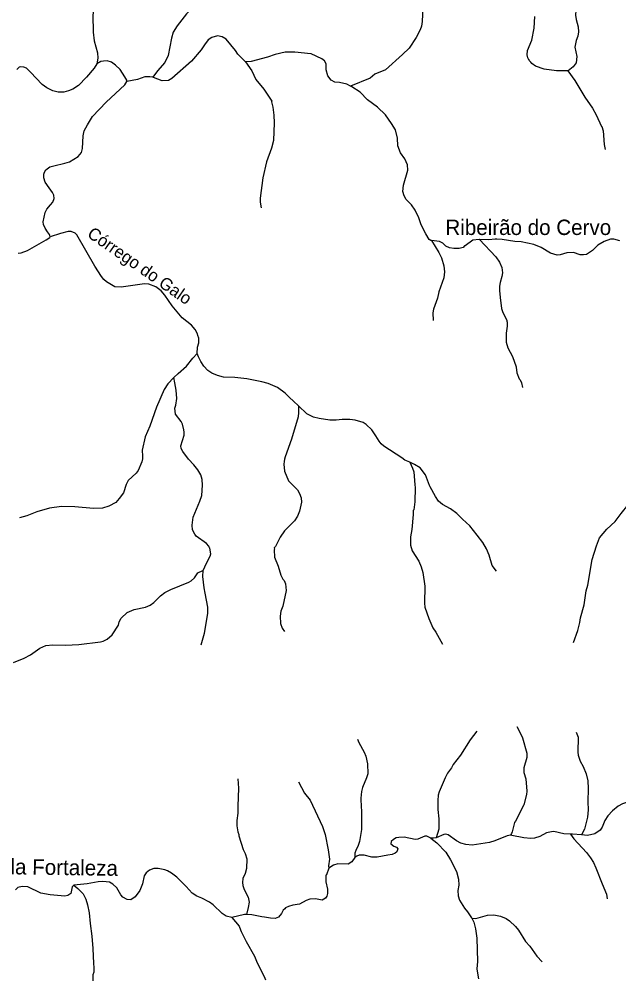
# Model space of a CAD drawing. Extents: x 396 to 422.2, y 7649.8 to 7677.6.
# Drawn here: x 409.11 to 413.01, y 7649.9 to 7656.16 of the extents above; entities that cross this region are included whole.
import ezdxf
from ezdxf.enums import TextEntityAlignment as Align

# ---------------------------------------------------------------- set-up
doc = ezdxf.new("R2010")
doc.units = 0
doc.header["$LTSCALE"] = 0.032
doc.layers.add('2', color=7, linetype='Continuous', lineweight=25)
doc.layers.add('7', color=7, linetype='Continuous', lineweight=25)
doc.layers.add('61', color=7, linetype='Continuous')

msp = doc.modelspace()

# ---------------------------------------------------------------- linework, layer by layer
at = {"layer": '2'}
for points in [[(409.6179, 7655.872), (409.5999, 7655.8432), (409.5497, 7655.7852), (409.4976, 7655.7301), (409.4602, 7655.7065), (409.4327, 7655.6957), (409.4032, 7655.6878), (409.3668, 7655.6878), (409.3314, 7655.6967), (409.2931, 7655.7164), (409.2626, 7655.737), (409.1869, 7655.8176), (409.1594, 7655.8432), (409.1417, 7655.8511), (409.123, 7655.853), (409.1131, 7655.8511), (409.0962, 7655.8359)], [(409.8123, 7655.7577), (409.8123, 7655.7665), (409.7995, 7655.7881), (409.768, 7655.8344), (409.7395, 7655.8639), (409.712, 7655.8835), (409.6844, 7655.8904), (409.6608, 7655.8894), (409.6431, 7655.8865), (409.6179, 7655.872)], [(409.1053, 7654.6387), (409.1259, 7654.6426), (409.1662, 7654.6564), (409.2882, 7654.7262), (409.3108, 7654.7409), (409.3137, 7654.7468), (409.3088, 7654.7616), (409.297, 7654.7793), (409.2813, 7654.8019), (409.2705, 7654.8255), (409.2675, 7654.8442), (409.2813, 7654.9051), (409.2921, 7654.9258), (409.3167, 7654.9533), (409.3314, 7654.971), (409.3393, 7654.9956), (409.3383, 7655.0162), (409.3295, 7655.0349), (409.3068, 7655.0644), (409.2823, 7655.1018), (409.2734, 7655.1303), (409.2724, 7655.1529), (409.2764, 7655.1667), (409.2852, 7655.1824), (409.3127, 7655.2011), (409.3383, 7655.209), (409.4101, 7655.2247), (409.4386, 7655.2336), (409.4956, 7655.269), (409.5183, 7655.2945), (409.5251, 7655.3201), (409.5291, 7655.4037), (409.535, 7655.4351), (409.5556, 7655.4754), (409.59, 7655.5295), (409.6775, 7655.6229), (409.7995, 7655.736), (409.8123, 7655.7577)]]:
    msp.add_lwpolyline(points, dxfattribs=at)
at = {"layer": '7'}
for points in [[(409.8043, 7656.6946), (409.791, 7656.6689), (409.7845, 7656.6465), (409.7771, 7656.5897), (409.7704, 7656.5671), (409.7494, 7656.5321), (409.6976, 7656.4627), (409.6654, 7656.4129), (409.6394, 7656.3547), (409.6319, 7656.3281), (409.6035, 7656.2649), (409.5969, 7656.2391), (409.5906, 7656.1891), (409.5938, 7656.0784), (409.6002, 7656.0219), (409.6225, 7655.9433), (409.624, 7655.9098), (409.6179, 7655.872)], [(410.6349, 7656.6002), (410.6027, 7656.5501), (410.6, 7656.5506), (410.5967, 7656.5421), (410.5554, 7656.4912), (410.5149, 7656.4492), (410.4637, 7656.3779), (410.4272, 7656.3448), (410.2668, 7656.2547), (410.2375, 7656.2342), (410.2, 7656.1964), (410.1399, 7656.12), (410.1127, 7656.0776), (410.1022, 7656.0384), (410.0814, 7655.9254), (410.0586, 7655.8798), (410.0128, 7655.8262), (409.9816, 7655.7845)], [(412.7824, 7656.4039), (412.7752, 7656.3967), (412.7632, 7656.3764), (412.7407, 7656.2937), (412.7406, 7656.2491), (412.7311, 7656.2184), (412.7302, 7656.1897), (412.7342, 7656.1594), (412.7469, 7656.1123), (412.7494, 7656.0809), (412.7438, 7656.0525), (412.7342, 7656.0238), (412.7264, 7655.9814), (412.7374, 7655.9201), (412.7341, 7655.8787), (412.7151, 7655.8515), (412.6816, 7655.8271), (412.6802, 7655.8271)], [(411.7396, 7656.2876), (411.7323, 7656.148), (411.7283, 7656.1172), (411.7206, 7656.0939), (411.6937, 7656.0436), (411.6475, 7655.9749), (411.6041, 7655.9316), (411.4941, 7655.8334), (411.4248, 7655.8048), (411.3936, 7655.7778), (411.2674, 7655.7264)], [(412.6802, 7655.8271), (412.6055, 7655.8268), (412.5261, 7655.8371), (412.4687, 7655.8576), (412.4456, 7655.8731), (412.4391, 7655.8834), (412.4299, 7655.8913), (412.4294, 7655.8969), (412.4263, 7655.8982), (412.4198, 7655.9113), (412.4153, 7655.9297), (412.4167, 7655.9581), (412.4465, 7656.0262), (412.4611, 7656.1045), (412.4663, 7656.18)], [(410.585, 7655.8843), (410.5844, 7655.8843), (410.5332, 7655.934), (410.5186, 7655.958), (410.4587, 7656.0328), (410.4319, 7656.0479), (410.4024, 7656.0543), (410.3643, 7656.0441), (410.3419, 7656.0291), (410.3168, 7655.9966), (410.2968, 7655.9625), (410.2323, 7655.8889), (410.106, 7655.7769), (410.084, 7655.7643)], [(411.2674, 7655.7264), (411.2424, 7655.7396), (411.1956, 7655.7499), (411.1644, 7655.7517), (411.1413, 7655.7649), (411.1183, 7655.7929), (411.1078, 7655.8321), (411.1087, 7655.8709), (411.0987, 7655.892), (411.0795, 7655.9048), (411.0108, 7655.9372), (411.0098, 7655.9377), (410.9037, 7655.9481), (410.8426, 7655.9472), (410.7777, 7655.9324), (410.7264, 7655.9151), (410.6208, 7655.8863), (410.585, 7655.8843)], [(410.585, 7655.8843), (410.6242, 7655.8273), (410.652, 7655.7702), (410.7027, 7655.7072), (410.7546, 7655.6299), (410.7534, 7655.6244), (410.7627, 7655.5907), (410.7692, 7655.5389), (410.7708, 7655.4876), (410.7652, 7655.3727), (410.7534, 7655.3227), (410.7214, 7655.2331), (410.6975, 7655.131), (410.6792, 7654.9969), (410.6802, 7654.9711), (410.6864, 7654.9353)], [(412.6802, 7655.8271), (412.7258, 7655.7629), (412.7908, 7655.6553), (412.8413, 7655.5833), (412.8644, 7655.5402), (412.8987, 7655.4649), (412.9017, 7655.4635), (412.9098, 7655.4354), (412.9169, 7655.3479), (412.9233, 7655.3149)], [(409.9816, 7655.7845), (409.961, 7655.788), (409.9302, 7655.788), (409.8812, 7655.7696), (409.8123, 7655.7577)], [(410.084, 7655.7643), (410.042, 7655.7612), (409.9866, 7655.7836), (409.9816, 7655.7845)], [(411.7934, 7654.7225), (411.7901, 7654.7229), (411.7789, 7654.729), (411.7564, 7654.7658), (411.727, 7654.8247), (411.7118, 7654.8691), (411.6878, 7654.9196), (411.6629, 7654.9546), (411.6288, 7654.9887), (411.6149, 7655.0127), (411.608, 7655.0413), (411.6121, 7655.0825), (411.6396, 7655.1803), (411.637, 7655.2149), (411.619, 7655.2547), (411.591, 7655.2926), (411.5737, 7655.3375), (411.572, 7655.3874), (411.5586, 7655.4428), (411.5341, 7655.4847), (411.4935, 7655.5398), (411.4413, 7655.5893), (411.3779, 7655.6384), (411.3292, 7655.6867), (411.2757, 7655.722), (411.2674, 7655.7264)], [(410.2706, 7653.986), (410.2715, 7654.0278), (410.2795, 7654.0572), (410.2795, 7654.0859), (410.2745, 7654.1042), (410.2718, 7654.1139), (410.2572, 7654.1421), (410.2328, 7654.171), (410.1731, 7654.2196), (410.1065, 7654.298), (410.0596, 7654.3668), (410.0359, 7654.3941), (410.0004, 7654.4216), (409.9558, 7654.4376), (409.9283, 7654.4399), (409.7762, 7654.4178), (409.7339, 7654.421), (409.6807, 7654.453), (409.6621, 7654.4689), (409.6474, 7654.4869), (409.604, 7654.5551), (409.4876, 7654.759), (409.4757, 7654.7693), (409.4514, 7654.7797), (409.4305, 7654.7799), (409.3813, 7654.7684), (409.3137, 7654.7468)], [(412.1051, 7654.7287), (412.1034, 7654.7288), (412.0627, 7654.7253), (412.0133, 7654.6879), (412.0075, 7654.6869), (411.9998, 7654.6774), (411.9731, 7654.6712), (411.9393, 7654.6698), (411.9104, 7654.6735), (411.8858, 7654.6857), (411.8681, 7654.7039), (411.8453, 7654.7165), (411.7934, 7654.7225)], [(411.7934, 7654.7225), (411.8417, 7654.6438), (411.8588, 7654.6098), (411.8736, 7654.5582), (411.8786, 7654.5182), (411.8734, 7654.4786), (411.841, 7654.389), (411.8315, 7654.3459), (411.8069, 7654.2748), (411.8028, 7654.2517), (411.8045, 7654.2016)], [(413.0181, 7654.7191), (412.9783, 7654.7302), (412.9575, 7654.7302), (412.9161, 7654.7159), (412.8744, 7654.6909), (412.8406, 7654.6564), (412.8012, 7654.6306), (412.7814, 7654.6282), (412.7602, 7654.6297), (412.7167, 7654.644), (412.6736, 7654.6409), (412.6303, 7654.6281), (412.6098, 7654.6267), (412.5681, 7654.6403), (412.5066, 7654.677), (412.4596, 7654.6952), (412.377, 7654.7135), (412.3359, 7654.7159), (412.253, 7654.7286), (412.218, 7654.731), (412.2074, 7654.7299), (412.1652, 7654.7255), (412.1051, 7654.7287)], [(412.1051, 7654.7287), (412.2121, 7654.6168), (412.2358, 7654.5819), (412.2497, 7654.5473), (412.2541, 7654.5126), (412.2516, 7654.4875), (412.239, 7654.4492), (412.2351, 7654.426), (412.2352, 7654.3975), (412.2408, 7654.3511), (412.2495, 7654.2797), (412.2557, 7654.2594), (412.2828, 7654.202), (412.2829, 7654.1946), (412.286, 7654.1924), (412.2862, 7654.1642), (412.2798, 7654.1196), (412.2799, 7654.0597), (412.2895, 7654.0243), (412.3202, 7653.9681), (412.3435, 7653.8993), (412.3436, 7653.8986), (412.3484, 7653.8619), (412.3629, 7653.821), (412.3707, 7653.8145), (412.3784, 7653.7959), (412.385, 7653.7662)], [(410.1183, 7653.8308), (410.1463, 7653.8568), (410.2012, 7653.9038), (410.242, 7653.9575), (410.2706, 7653.986)], [(410.9288, 7653.6457), (410.8961, 7653.6768), (410.8696, 7653.701), (410.8421, 7653.7284), (410.7931, 7653.7653), (410.7317, 7653.7914), (410.6892, 7653.8032), (410.5935, 7653.8212), (410.5148, 7653.8315), (410.4403, 7653.8331), (410.4022, 7653.8426), (410.3661, 7653.8587), (410.3398, 7653.8771), (410.3136, 7653.9043), (410.2927, 7653.9353), (410.2774, 7653.9655), (410.2706, 7653.986)], [(410.1183, 7653.8308), (410.0799, 7653.7891), (410.0551, 7653.7517), (410.0062, 7653.6381), (409.9628, 7653.5146), (409.931, 7653.4444), (409.9112, 7653.3574), (409.9115, 7653.355), (409.9151, 7653.3207), (409.9143, 7653.3012), (409.9094, 7653.2817), (409.8863, 7653.2261), (409.8733, 7653.2075), (409.8219, 7653.1608), (409.8077, 7653.1344), (409.7899, 7653.0811), (409.7622, 7653.0422), (409.7404, 7653.0173), (409.6956, 7652.9931), (409.6534, 7652.9811), (409.5961, 7652.9791), (409.4749, 7652.9885), (409.3885, 7652.9902), (409.3098, 7652.9797), (409.2279, 7652.9571), (409.1612, 7652.931), (409.1137, 7652.9176)], [(410.306, 7652.5744), (410.3086, 7652.5756), (410.3294, 7652.6231), (410.3552, 7652.6669), (410.3593, 7652.6821), (410.3531, 7652.7195), (410.3493, 7652.7215), (410.3448, 7652.734), (410.3308, 7652.7498), (410.2642, 7652.7987), (410.2539, 7652.8103), (410.2398, 7652.839), (410.2374, 7652.8686), (410.2431, 7652.9223), (410.2874, 7653.0265), (410.3003, 7653.0632), (410.3043, 7653.1307), (410.3018, 7653.1664), (410.2925, 7653.1972), (410.2737, 7653.2297), (410.2482, 7653.2616), (410.2131, 7653.2982), (410.176, 7653.3493), (410.1658, 7653.3678), (410.1633, 7653.3861), (410.1854, 7653.4559), (410.1845, 7653.4752), (410.1838, 7653.4909), (410.1743, 7653.526), (410.1657, 7653.5433), (410.1281, 7653.5915), (410.1249, 7653.6302), (410.1319, 7653.6513), (410.1377, 7653.6929), (410.1329, 7653.7474), (410.1248, 7653.7957), (410.1183, 7653.8308)], [(410.9288, 7653.6457), (410.9287, 7653.6019), (410.9255, 7653.5739), (410.8822, 7653.4296), (410.8417, 7653.3136), (410.8382, 7653.2988), (410.8347, 7653.2839), (410.8338, 7653.2676), (410.8383, 7653.2212), (410.8645, 7653.1574), (410.9222, 7653.0994), (410.9358, 7653.0765), (410.9462, 7653.0475), (410.9486, 7653.0201), (410.9349, 7652.9607), (410.9223, 7652.9288), (410.9022, 7652.8974), (410.8376, 7652.8336), (410.8091, 7652.7907), (410.7785, 7652.7313), (410.7705, 7652.7211), (410.7723, 7652.7143), (410.7693, 7652.7082), (410.7727, 7652.6624), (410.7966, 7652.6018), (410.8134, 7652.5444), (410.8277, 7652.5173), (410.8345, 7652.51), (410.8432, 7652.4884), (410.8488, 7652.4439), (410.8265, 7652.3427), (410.8139, 7652.309), (410.8092, 7652.2779), (410.8117, 7652.2302), (410.8223, 7652.1998), (410.8371, 7652.1776)], [(411.6515, 7653.2786), (411.6199, 7653.2919), (411.6004, 7653.3079), (411.4832, 7653.3831), (411.4668, 7653.3979), (411.4526, 7653.4161), (411.4313, 7653.4515), (411.4193, 7653.4715), (411.4059, 7653.489), (411.3692, 7653.5258), (411.3495, 7653.5382), (411.2971, 7653.5539), (411.2629, 7653.5571), (411.2132, 7653.5572), (411.1735, 7653.5524), (411.132, 7653.5533), (411.0619, 7653.5628), (411.0265, 7653.5727), (410.9833, 7653.5938), (410.9288, 7653.6457)], [(412.7171, 7652.1064), (412.7443, 7652.185), (412.7581, 7652.237), (412.7631, 7652.267), (412.7868, 7652.3514), (412.7997, 7652.4418), (412.8091, 7652.479), (412.8388, 7652.646), (412.8653, 7652.7356), (412.8867, 7652.7863), (412.9339, 7652.8428), (412.9883, 7652.8926), (413.0263, 7652.9447), (413.0726, 7653.0011), (413.126, 7653.0845), (413.1866, 7653.1713), (413.2069, 7653.2004), (413.2412, 7653.2302), (413.3003, 7653.2714), (413.385, 7653.345), (413.4347, 7653.3755), (413.4773, 7653.4071), (413.5161, 7653.4482), (413.5912, 7653.5629)], [(411.6515, 7653.2786), (411.6707, 7653.2399), (411.6782, 7653.2157), (411.6849, 7653.1317), (411.6863, 7653.1142), (411.6841, 7653.0222), (411.6783, 7652.9697), (411.6752, 7652.9643), (411.6751, 7652.94), (411.6648, 7652.8415), (411.6561, 7652.7927), (411.6565, 7652.7384), (411.6687, 7652.7033), (411.7117, 7652.6363), (411.7269, 7652.598), (411.7374, 7652.5611), (411.7501, 7652.4721), (411.7469, 7652.3622), (411.751, 7652.3362), (411.7761, 7652.2616), (411.8013, 7652.2015), (411.8215, 7652.173), (411.8659, 7652.0962)], [(412.2151, 7652.5694), (412.1887, 7652.6077), (412.1686, 7652.6735), (412.1513, 7652.7158), (412.1263, 7652.7569), (412.0911, 7652.8053), (412.0421, 7652.8648), (411.9939, 7652.9082), (411.9586, 7652.9452), (411.9159, 7652.9769), (411.8656, 7653.0031), (411.839, 7653.025), (411.8189, 7653.0552), (411.7848, 7653.1191), (411.7806, 7653.127), (411.7533, 7653.1975), (411.7196, 7653.2423), (411.6834, 7653.2651), (411.6515, 7653.2786)], [(409.0744, 7651.9752), (409.1454, 7652.0047), (409.1865, 7652.025), (409.246, 7652.069), (409.2867, 7652.0859), (409.3323, 7652.0905), (409.414, 7652.089), (409.5001, 7652.0923), (409.6419, 7652.1106), (409.6587, 7652.115), (409.6836, 7652.1277), (409.7178, 7652.1565), (409.758, 7652.2184), (409.7626, 7652.2408), (409.7754, 7652.2641), (409.8136, 7652.3009), (409.861, 7652.3208), (409.9347, 7652.3353), (409.9634, 7652.348), (409.9875, 7652.3669), (410.0307, 7652.4095), (410.0597, 7652.4312), (410.0934, 7652.4488), (410.099, 7652.4517), (410.2164, 7652.4984), (410.2301, 7652.5068), (410.2522, 7652.5265), (410.2743, 7652.5596), (410.306, 7652.5744)], [(410.306, 7652.5744), (410.3051, 7652.5364), (410.3133, 7652.4622), (410.3197, 7652.4279), (410.3368, 7652.3369), (410.337, 7652.2964), (410.3162, 7652.1636), (410.294, 7652.0882)], [(412.3476, 7651.5603), (412.373, 7651.5147), (412.3848, 7651.4863), (412.4135, 7651.3863), (412.4136, 7651.3568), (412.3945, 7651.2893), (412.3946, 7651.2608), (412.4058, 7651.2178), (412.4128, 7651.1387), (412.4121, 7651.1158), (412.3928, 7651.0487), (412.3387, 7650.9438), (412.334, 7650.9346), (412.3188, 7650.874), (412.3132, 7650.8626), (412.3075, 7650.8517)], [(412.0892, 7651.53), (412.0446, 7651.472), (411.9818, 7651.373), (411.9352, 7651.3129), (411.9236, 7651.2912), (411.8984, 7651.2548), (411.8825, 7651.2244), (411.844, 7651.1345), (411.8378, 7651.1125), (411.8346, 7651.0767), (411.8347, 7651.0184), (411.841, 7650.9588), (411.841, 7650.8911), (411.8236, 7650.8355)], [(412.7351, 7651.522), (412.7469, 7651.4892), (412.7454, 7651.3919), (412.7475, 7651.373), (412.7596, 7651.3348), (412.7799, 7651.2999), (412.8, 7651.2505), (412.8092, 7651.2057), (412.8124, 7651.1555), (412.8093, 7651.0693), (412.8124, 7651.0175), (412.8083, 7650.9701), (412.7883, 7650.8908), (412.7684, 7650.8539)], [(411.3124, 7651.4774), (411.321, 7651.4544), (411.3553, 7651.3919), (411.3655, 7651.3671), (411.3777, 7651.3158), (411.3784, 7651.2509), (411.3718, 7651.2248), (411.3452, 7651.1625), (411.3387, 7651.1371), (411.333, 7651.0938), (411.3355, 7651.0312), (411.3387, 7651.0158), (411.3386, 7650.8892), (411.3242, 7650.8113), (411.3163, 7650.7858), (411.3018, 7650.7527), (411.294, 7650.7348), (411.2953, 7650.7079)], [(410.5348, 7651.219), (410.5387, 7651.1579), (410.5332, 7651.0414), (410.5347, 7650.9957), (410.5287, 7650.9467), (410.5287, 7650.912), (410.5348, 7650.8737), (410.5411, 7650.8573), (410.5413, 7650.8475), (410.5696, 7650.7594), (410.5825, 7650.7335), (410.5921, 7650.6981), (410.5913, 7650.6352), (410.5821, 7650.6031), (410.567, 7650.57), (410.5634, 7650.5444), (410.5667, 7650.5242), (410.5761, 7650.499), (410.6021, 7650.4482), (410.6081, 7650.4159), (410.6004, 7650.3809), (410.5905, 7650.3357)], [(410.9288, 7651.1982), (410.9678, 7651.1262), (411.0048, 7651.0799), (411.084, 7650.9078), (411.101, 7650.8573), (411.1225, 7650.7575), (411.1298, 7650.6953), (411.1234, 7650.6535), (411.1249, 7650.6368)], [(413.5185, 7651.0717), (413.357, 7651.0745), (413.2422, 7651.0809), (413.1311, 7651.0785), (413.07, 7651.0677), (413.0676, 7651.0673), (413.0354, 7651.0561), (413.0064, 7651.0406), (412.9711, 7651.0107), (412.9408, 7650.9788), (412.9207, 7650.9466), (412.9041, 7650.904), (412.8908, 7650.8852), (412.8561, 7650.8604), (412.8071, 7650.8505), (412.7684, 7650.8539)], [(412.3075, 7650.8517), (412.2854, 7650.8481), (412.2047, 7650.8149), (412.1704, 7650.8044), (412.0588, 7650.7875), (412.0163, 7650.7914), (411.9851, 7650.8002), (411.9556, 7650.8155), (411.9024, 7650.8544), (411.8876, 7650.8584), (411.8738, 7650.8574), (411.8236, 7650.8355)], [(412.6971, 7650.8592), (412.654, 7650.8599), (412.5891, 7650.8751), (412.5728, 7650.8743), (412.5409, 7650.8663), (412.4973, 7650.8427), (412.4633, 7650.8329), (412.4389, 7650.8314), (412.394, 7650.8355), (412.3154, 7650.8502), (412.3075, 7650.8517)], [(412.6971, 7650.8592), (412.7195, 7650.8276), (412.801, 7650.7399), (412.8281, 7650.7048), (412.8468, 7650.6739), (412.8628, 7650.6404), (412.9028, 7650.5347), (412.932, 7650.4689), (412.9353, 7650.4374)], [(412.7684, 7650.8539), (412.7107, 7650.859), (412.6971, 7650.8592)], [(411.7891, 7650.8329), (411.7635, 7650.8457), (411.7495, 7650.845), (411.7042, 7650.8259), (411.6871, 7650.8242), (411.6165, 7650.8384), (411.5808, 7650.8376), (411.5636, 7650.8345), (411.5458, 7650.8247), (411.5306, 7650.8104), (411.5285, 7650.7962), (411.5477, 7650.7807), (411.5666, 7650.7746), (411.5745, 7650.763), (411.5686, 7650.7443), (411.5579, 7650.7353), (411.5375, 7650.7253), (411.509, 7650.7228), (411.4395, 7650.7094)], [(411.8236, 7650.8355), (411.807, 7650.8319), (411.7891, 7650.8329)], [(411.7891, 7650.8329), (411.8278, 7650.8024), (411.8867, 7650.7417), (411.918, 7650.6911), (411.955, 7650.6155), (411.9685, 7650.5648), (411.9718, 7650.5271), (411.9655, 7650.4912), (411.9663, 7650.457), (411.9756, 7650.4287), (412.0083, 7650.3762), (412.0273, 7650.3532), (412.0526, 7650.3152), (412.056, 7650.311)], [(411.2953, 7650.7079), (411.2944, 7650.7074), (411.2761, 7650.679), (411.2516, 7650.6642), (411.1834, 7650.6646), (411.1552, 7650.6574), (411.1249, 7650.6368)], [(411.4395, 7650.7094), (411.4044, 7650.71), (411.3546, 7650.722), (411.3225, 7650.7227), (411.3078, 7650.7147), (411.2953, 7650.7079)], [(410.4948, 7650.3158), (410.4585, 7650.3245), (410.4313, 7650.3425), (410.3731, 7650.3988), (410.3503, 7650.417), (410.3003, 7650.4429), (410.2678, 7650.4545), (410.2365, 7650.4757), (410.1991, 7650.5178), (410.1383, 7650.5778), (410.1038, 7650.6048), (410.0777, 7650.6204), (410.0598, 7650.627), (410.0171, 7650.6343), (409.9877, 7650.6343), (409.9592, 7650.6243), (409.9391, 7650.6072), (409.9251, 7650.587), (409.9133, 7650.5363), (409.8968, 7650.4927), (409.867, 7650.4507), (409.8385, 7650.431), (409.8136, 7650.4335), (409.7868, 7650.4494), (409.7739, 7650.463), (409.7474, 7650.5086), (409.7215, 7650.5342), (409.7004, 7650.5466), (409.6572, 7650.5514), (409.6253, 7650.5489), (409.5535, 7650.5362), (409.467, 7650.5278)], [(411.1249, 7650.6368), (411.1104, 7650.5939), (411.1074, 7650.5916), (411.1074, 7650.5479), (411.1168, 7650.5011), (411.117, 7650.4733), (411.1129, 7650.4558), (411.1032, 7650.4428), (411.0815, 7650.4302), (411.0388, 7650.4373), (411.0013, 7650.4365), (410.9783, 7650.4269), (410.9358, 7650.4025), (410.8913, 7650.3965), (410.8633, 7650.3887), (410.8441, 7650.3789), (410.8407, 7650.3726), (410.8299, 7650.3647), (410.818, 7650.3427), (410.7993, 7650.3178), (410.776, 7650.3106), (410.7473, 7650.3113), (410.7071, 7650.3175), (410.6892, 7650.3202), (410.6261, 7650.3345), (410.5905, 7650.3357)], [(409.467, 7650.5278), (409.4565, 7650.5156), (409.4486, 7650.4728), (409.4281, 7650.4606), (409.4087, 7650.4549), (409.313, 7650.4636), (409.2542, 7650.4754), (409.1682, 7650.5153), (409.1311, 7650.5186), (409.1044, 7650.5124), (409.0875, 7650.4962)], [(409.467, 7650.5278), (409.4943, 7650.5057), (409.5281, 7650.4703), (409.5457, 7650.4352), (409.5571, 7650.3995), (409.5666, 7650.3476), (409.5729, 7650.2774), (409.5857, 7650.1941), (409.5921, 7650.1147), (409.5951, 7650.0177), (409.5986, 7649.9908), (409.5969, 7649.9613), (409.5914, 7649.9424), (409.5922, 7649.9079), (409.5923, 7649.9046)], [(410.5905, 7650.3357), (410.5774, 7650.3361), (410.4948, 7650.3158)], [(410.4948, 7650.3158), (410.5428, 7650.2608), (410.5522, 7650.237), (410.5567, 7650.226), (410.5876, 7650.1604), (410.6418, 7650.0646), (410.6546, 7650.0327), (410.7087, 7649.9206), (410.7135, 7649.9107)], [(412.056, 7650.311), (412.0827, 7650.3098), (412.1573, 7650.3321), (412.1989, 7650.3345), (412.2419, 7650.3253), (412.2792, 7650.3088), (412.2999, 7650.2952), (412.3402, 7650.2584), (412.3601, 7650.2338), (412.4055, 7650.1593), (412.4318, 7650.129), (412.4776, 7650.0657), (412.5126, 7650.0275)], [(412.056, 7650.311), (412.0691, 7650.285), (412.0804, 7650.242), (412.0883, 7650.1817), (412.0931, 7650.0301), (412.0876, 7649.9817), (412.0963, 7649.9286), (412.098, 7649.9182)]]:
    msp.add_lwpolyline(points, dxfattribs=at)

# ---------------------------------------------------------------- texts
at = {"layer": '61'}
msp.add_text('Ribeirão do Cervo', height=0.1, dxfattribs=at).set_placement((412.4227, 7654.758), align=Align.CENTER)
for s, height, rotation, p in [('Córrego do Galo', 0.08, 325.29, (409.8738, 7654.5252)), ('Córrego da Fortaleza', 0.1, 359.165, (409.122, 7650.5965))]:
    msp.add_text(s, height=height, rotation=rotation, dxfattribs=at).set_placement(p, align=Align.CENTER)

doc.saveas('drawing.dxf')
